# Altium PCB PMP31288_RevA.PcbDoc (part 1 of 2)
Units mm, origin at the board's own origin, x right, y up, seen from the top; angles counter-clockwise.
Board outline 73.66 x 62.23 mm, 2 copper layers (Top Layer, Bottom Layer), stack 1.575 mm thick; 96 components, 44 nets, 195 pads, 25 vias.
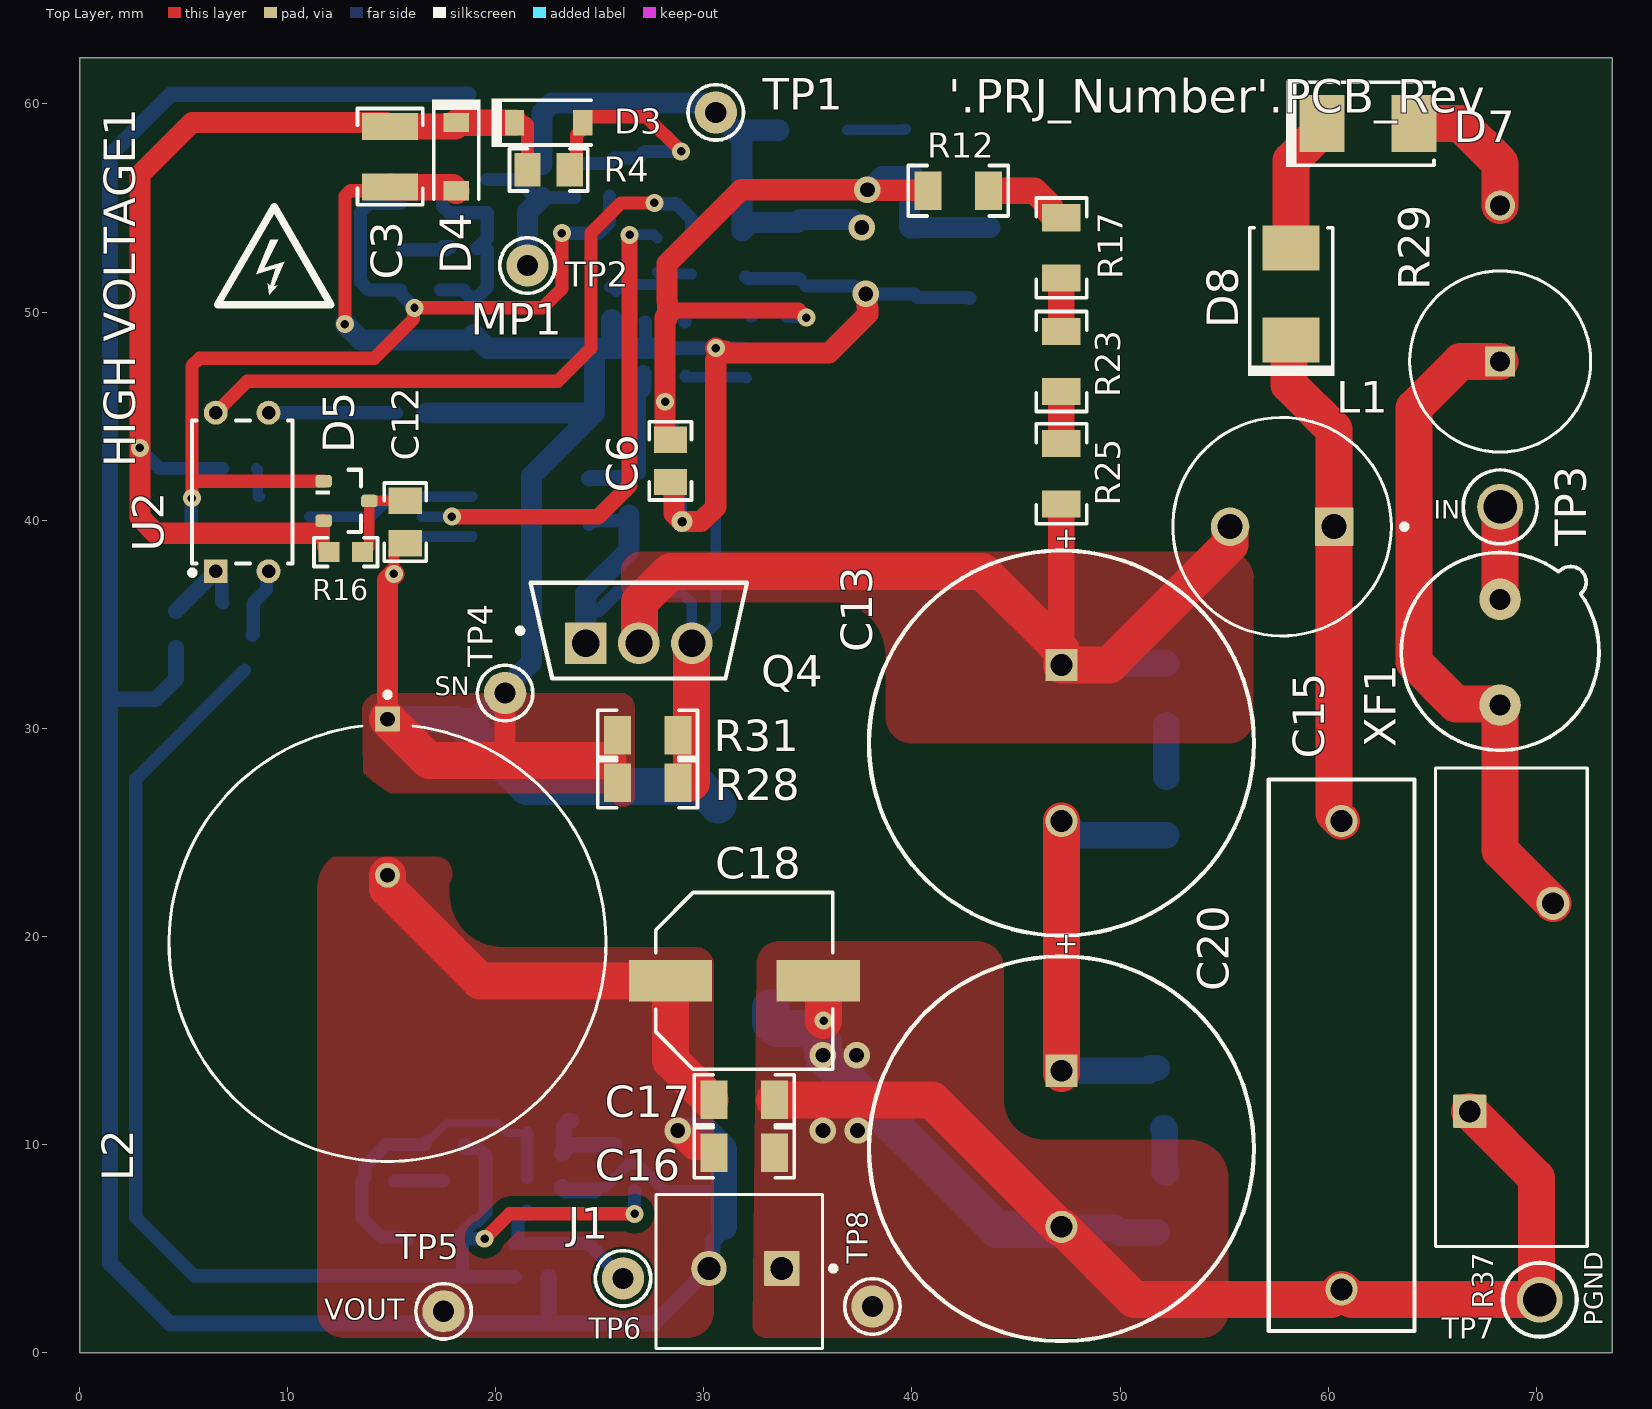
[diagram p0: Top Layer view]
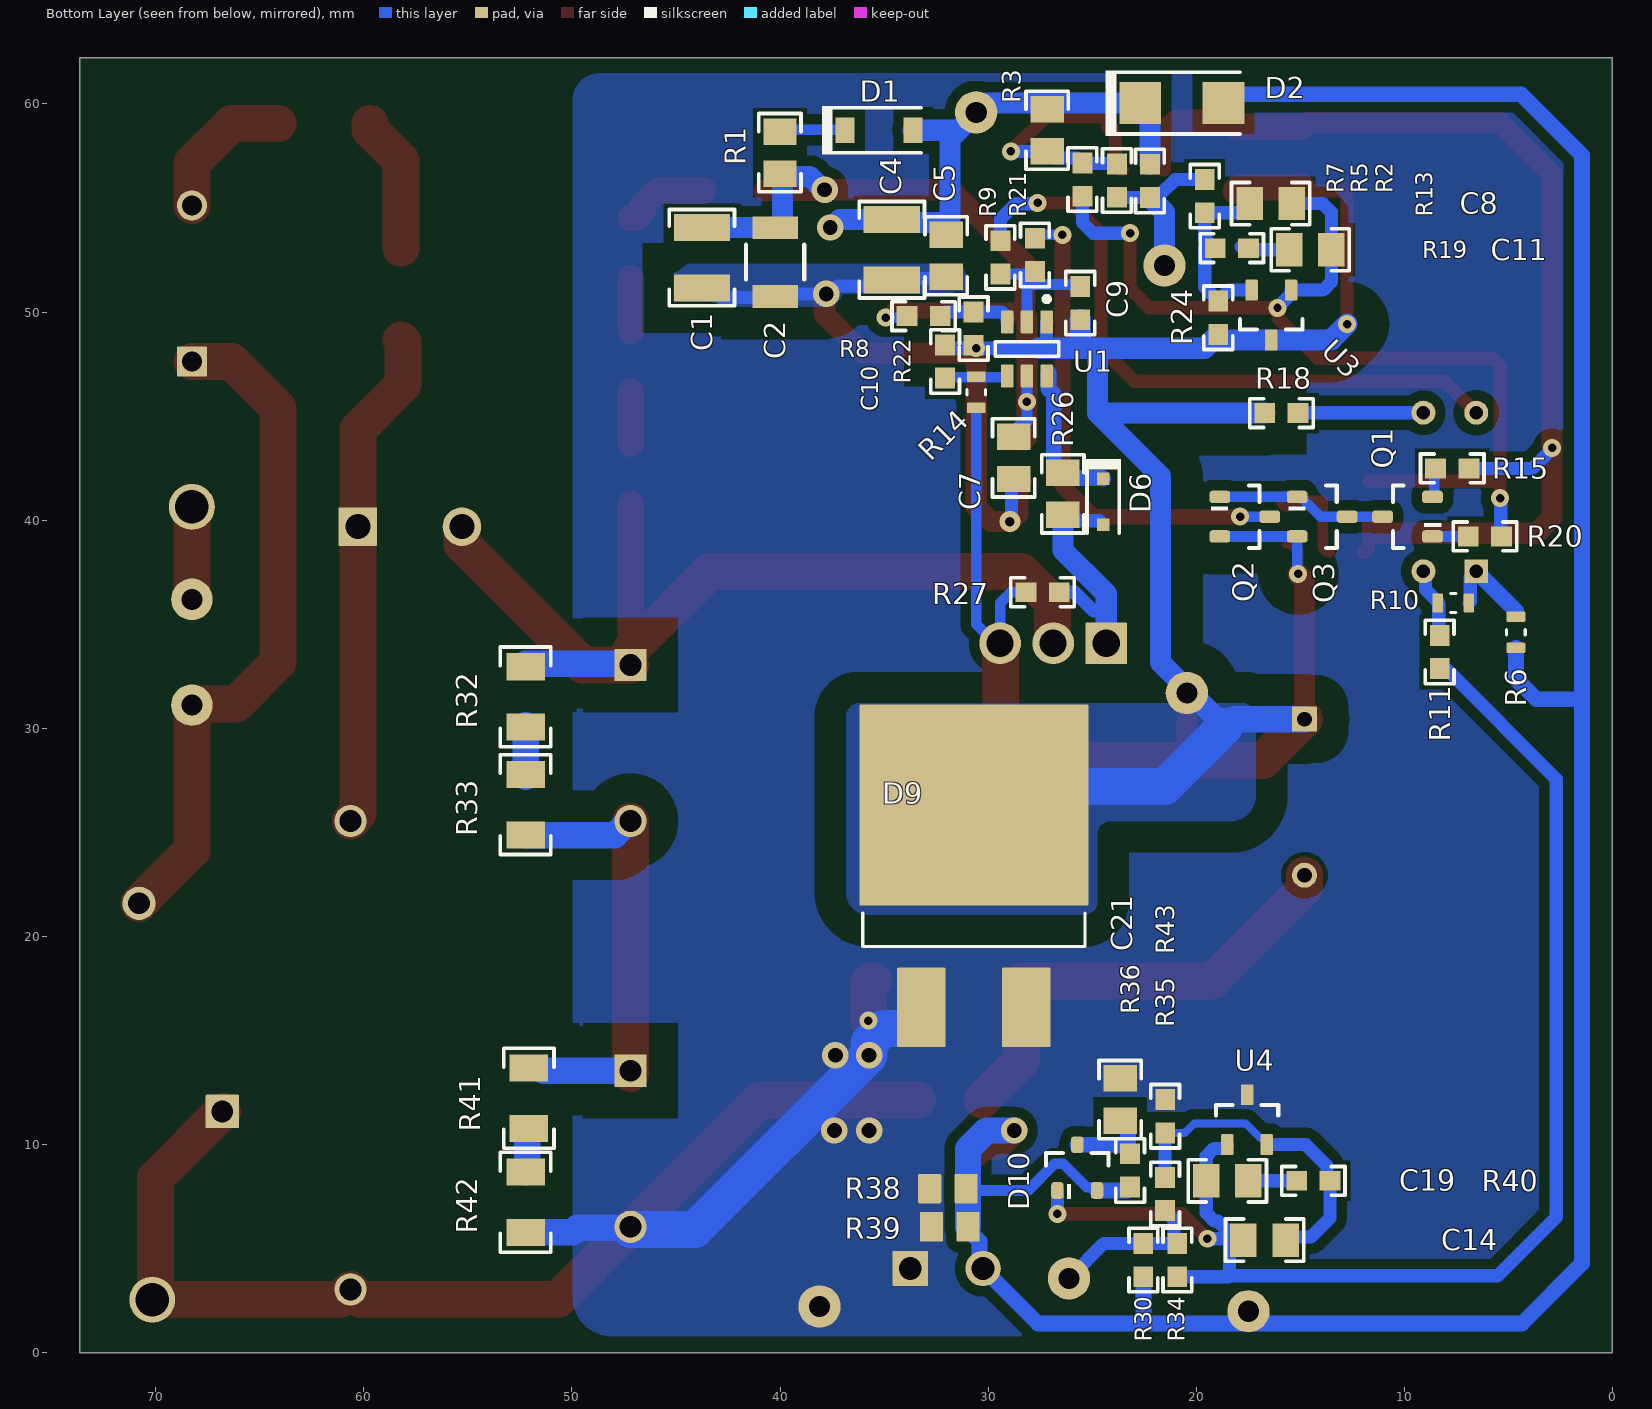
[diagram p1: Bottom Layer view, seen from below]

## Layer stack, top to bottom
Top Solder: solder mask 0.0102, Solder Resist, Dk 3.5
Top Layer: signal copper 0.0356
Dielectric1: core 1.5037, FR-4 High Tg, Dk 4.8
Bottom Layer: signal copper 0.0356
Bottom Solder: solder mask 0.0102, Solder Resist, Dk 3.5

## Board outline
0,0 73.66,0 73.66,62.23 0,62.23

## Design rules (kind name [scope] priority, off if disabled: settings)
AcuteAngle [All] p1: minimum=4.50000000000000E+0001 checktracksonly=FALSE
AssemblyTestPointUsage [All] p1: valid=2
BoardOutlineClearance BoardOutlineClearance_MountingHoles [OnCopper and InComponentClass('Mounting Holes')] p1: gap=1 ignorepadtopadclearanceinfootprint=FALSE
BoardOutlineClearance BoardOutlineClearance_Poly [OnCopper and IsPoly] p2: gap=0.635 ignorepadtopadclearanceinfootprint=FALSE
BoardOutlineClearance [OnCopper and Not InComponentClass('Logo') and not InComponentClass('FiducialMark') and not InRegion(1000,500,4000,800) and not InPoly] p3: gap=0.889 ignorepadtopadclearanceinfootprint=FALSE
Clearance Clearance_SN [InNet('SN') vs InNet('PGND')] p1: gap=1.524 ignorepadtopadclearanceinfootprint=TRUE
Clearance Clearance_C13_1 [InNet('NetC13_1') vs InNet('PGND')] p2: gap=1.524 ignorepadtopadclearanceinfootprint=TRUE
Clearance Clearance_C13_2 [InNet('NetC13_2') vs InNet('PGND')] p3: gap=1.524 ignorepadtopadclearanceinfootprint=TRUE
Clearance Clearance_Keepouts [((IsTrack Or IsArc) And Not InPoly) And IsFree and IsKeepOut vs ((IsTrack Or IsArc) And Not InPoly) And IsFree and IsKeepOut] p4: gap=0 ignorepadtopadclearanceinfootprint=FALSE
Clearance Clearance_Poly [InPolygon] p5: gap=0.508 ignorepadtopadclearanceinfootprint=TRUE
Clearance Clearance_FiducialMark [IsKeepOut and InComponentClass('FiducialMark') vs IsPad and InComponentClass('FiducialMark')] p6: gap=0 ignorepadtopadclearanceinfootprint=FALSE
Clearance [All] p7: gap=0.2 ignorepadtopadclearanceinfootprint=TRUE
ComponentClearance ComponentClearance_MountingHoles_FiducialMarks [InComponentClass('Mounting Holes') vs InComponentClass('FiducialMark')] p1: gap=1.27 collisioncheckmode=3 verticalgap=0.254 showdistances=FALSE
ComponentClearance ComponentClearance_Shunt [InComponentClass('Header') vs InComponentClass('Shunt')] p2: gap=0 collisioncheckmode=3 verticalgap=0 showdistances=FALSE
ComponentClearance ComponentClearance_Logo [InComponentClass('Logo')] p3: gap=0.762 collisioncheckmode=3 verticalgap=0.254 showdistances=FALSE
ComponentClearance ComponentClearance_ScrewToNut [(HasFootprint('NY PMS 440 0025 PH')) vs (HasFootprint('Keystone_1902C'))] p4: gap=0.127 collisioncheckmode=3 verticalgap=0.254 showdistances=FALSE
ComponentClearance ComponentClearance_MountingHoles [InComponentClass('Mounting Holes')] p5: gap=2.54 collisioncheckmode=3 verticalgap=2540 showdistances=FALSE
ComponentClearance ComponentClearance_SmallPassives [HasFootprint('0201*') or HasFootprint('0402*') or HasFootprint('0508') or HasFootprint('0603*') or HasFootprint('0612') or HasFootprint('0805*') or HasFootprint('0815*') or HasFootprint('0830*') or HasFootprint('1206*') or HasFootprint('1210*') or HasFootprint('1808*') or HasFootprint('1812*') or HasFootprint('1825*') or HasFootprint('2010*') or HasFootprint('2220*') or HasFootprint('2225*') or HasFootprint('2512*') or HasFootprint('2728*') or HasFootprint('3518*') vs HasFootprint('0201*') or HasFootprint('0402*') or HasFootprint('0508') or HasFootprint('0603*') or HasFootprint('0612') or HasFootprint('0805*') or HasFootprint('0815*') or HasFootprint('0830*') or HasFootprint('1206*') or HasFootprint('1210*') or HasFootprint('1808*') or HasFootprint('1812*') or HasFootprint('1825*') or HasFootprint('2010*') or HasFootprint('2220*') or HasFootprint('2225*') or HasFootprint('2512*') or HasFootprint('2728*') or HasFootprint('3518*')] p6: gap=0.38 collisioncheckmode=3 verticalgap=0.254 showdistances=FALSE
ComponentClearance ComponentClearance_THtoSMT [IsThruComponent vs IsSMTComponent] p7: gap=0.762 collisioncheckmode=3 verticalgap=0.762 showdistances=FALSE
ComponentClearance ComponentClearance_THtoTH [IsThruComponent vs IsThruComponent] p8: gap=0.508 collisioncheckmode=3 verticalgap=0.762 showdistances=FALSE
ComponentClearance [All] p9: gap=0.508 collisioncheckmode=3 verticalgap=0.254 showdistances=FALSE
DiffPairsRouting [All] p1: maxlimit=2.54 minlimit=0.254 mostfreqgap=0.254 toplayer_minwidth=0.381 toplayer_maxwidth=0.381 toplayer_prefwidth=0.381 bottomlayer_minwidth=0.381 bottomlayer_maxwidth=0.381 bottomlayer_prefwidth=0.381 maxuncoupledlength=25.4
FabricationTestPointUsage TestPointUsage [All] p1: valid=2 allowmultiple=FALSE
FabricationTestpoint Testpoint [All] p1: side=3 testpointundercomponent=TRUE minsize=1.016 maxsize=2.54 preferedsize=1.524 minholesize=0 maxholesize=1.016 preferedholesize=0.813 testpointgrid=0.025 allowsidetop=TRUE allowsidebottom=TRUE usegrid=TRUE gridtolerance=0
FanoutControl Fanout_LCC [IsLCC] p1: bgadir=Out bgaviamode=Centered fanoutstyle=Auto fanoutdirection=Alternating viagrid=0.025 // Fanout_LCC (Default Rule)
FanoutControl Fanout_BGA [IsBGA] p2: bgadir=Out bgaviamode=Centered fanoutstyle=Auto fanoutdirection=Alternating viagrid=0.025 // Fanout_BGA (Default Rule)
FanoutControl Fanout_Default [All] p4: bgadir=Out bgaviamode=Centered fanoutstyle=Auto fanoutdirection=Alternating viagrid=0.025 // Fanout_Default (Default Rule)
FanoutControl Fanout_Small [(CompPinCount < 5)] p5: bgadir=Out bgaviamode=Centered fanoutstyle=Auto fanoutdirection=OutThenIn viagrid=0.025 // Fanout_Small (Default Rule)
HoleSize [All] p1: absolutevalues=TRUE maxlimit=6.375 minlimit=0.2 maxpercent=80.000 minpercent=20.000
MinimumAnnularRing MinimumAnnularRing_ThermalPadVias [IsVia and InAnyComponent] p1: minimumring=0.15
MinimumAnnularRing [All] p2: minimumring=0.2
MinimumSolderMaskSliver MinimumSolderMaskSliver_Logo [InComponentClass('Logo') vs InComponentClass('Logo')] p1: minsoldermaskwidth=0.018
MinimumSolderMaskSliver [All] p2: minsoldermaskwidth=0.1
PlaneConnect [All] p1: planeconnectstyle=Relief reliefexpansion=0.254 reliefentries=4 reliefconductorwidth=0.254 reliefairgap=0.254
PolygonConnect [All] p1: connectstyle=Direct reliefconductorwidth=0.254 reliefentries=4 polygonreliefangle="90 Angle" airgapwidth=0.254
RoutingVias ThermalPadVias [IsVia and InAnyComponent] p1: holewidth=0.2 width=0.5 viastyle="Through Hole" minholewidth=0.2 minwidth=0.5 maxholewidth=0.33 maxwidth=0.6
RoutingVias [All] p2: holewidth=0.406 width=0.864 viastyle="Through Hole" minholewidth=0.2 minwidth=0.61 maxholewidth=1.016 maxwidth=1.651
SilkToBoardRegionClearance [Not ((IsComment or IsDesignator) And (Hide <> 'False')) and not InRegion(1000,500,4000,800)] p1:
SilkToSilkClearance SilkToSilkClearance_Pb-FreeLogo [(HasFootprint('Pb-Free_Overlay_Medium') OR HasFootprint('Pb-Free_Overlay_Small')) vs (HasFootprint('Pb-Free_Overlay_Medium') OR HasFootprint('Pb-Free_Overlay_Small'))] p1 off: silktosilkclearance=0
SilkToSilkClearance [All] p2 off: silktosilkclearance=0.1
SilkToSolderMaskClearance SilkToComponentPadClearance [(IsPad or IsFill or IsRegion) and InAnycomponent] p1 off: minsilkscreentomaskgap=0.127 clearancetoexposedcopper=TRUE
SilkToSolderMaskClearance "Silk to Solder Mask Opening" [All] p2 off: minsilkscreentomaskgap=0.1 clearancetoexposedcopper=FALSE
SolderMaskExpansion [All] p1: expansion=0.05 istentingtop=FALSE
UnRoutedNet [All] p1: checkbadconnections=TRUE
Width [All] p1: maxlimit=2.54 minlimit=0.152 preferedwidth=0.254 checkconnectedcopper=TRUE
14 further rules are at their usual default settings.

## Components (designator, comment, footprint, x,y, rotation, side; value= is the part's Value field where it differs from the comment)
C1 "DNPC3225X7R1H105K160AA" 1210_180 43.756,52.614 r270 bottom value=DNP
C2 "C3225X7R1H106M250AC" 1210_280 40.234,52.403 r270 bottom value=10uF
C3 "C3225X7R1H105K160AA" 1210_180 14.922,57.468 r270 top value=1uF
C4 "DNPC3225X7R1H105K160AA" 1210_180 34.63,52.995 r270 bottom value=DNP
C5 "GRM21BR71H224KA01L" 0805_HV 32.017,52.706 r270 bottom value=0.22uF
C6 "C0805C104J5RACTU" 0805_HV 28.394,42.851 r270 top value=1uF
C7 "C0805C104J5RACTU" 0805_HV 28.773,42.994 r270 bottom value=0.1uF
C8 "DNP08055C473KAT2A" 0805_HV 16.422,55.214 r180 bottom value=DNP
C9 "DNP" 0603 25.575,50.428 r270 bottom
C10 "C0603C391K5RACTU" 0603 32.067,47.625 r90 bottom value=390pF
C11 "08055C473KAT2A" 0805_HV 14.522,52.995 r180 bottom value=0.047uF
C12 "GRM21BR71H224KA01L" 0805_HV 15.65,39.911 r270 top value=0.22uF
C13 "UCS2W330MHD6" UCS_1800x2000 47.184,29.29 r270 top value=33uF
C14 "DNP08055C473KAT2A" 0805_HV 16.716,5.402 r0 bottom value=DNP
C15 "B32913C5104K000" B32913_2650x700x1600 60.642,14.287 r270 top value=0.1uF
C16 "GCM31MR71E105KA37L" 1206 31.944,9.605 r0 top value=DNP
C17 "GCM31MR71E105KA37L" 1206 31.944,12.145 r0 top value=DNP
C18 "EEE-FK1E331P" SM_RADIAL_F 31.944,17.86 r0 top value=330uF
C19 "08055C473KAT2A" 0805_HV 18.506,8.255 r0 bottom value=0.047uF
C20 "UCS2W330MHD6" UCS_1800x2000 47.184,9.795 r270 top value=33uF
C21 "GRM21BR71H105KA12L" 0805_HV 23.652,12.157 r90 bottom value=1uF
D1 "1N4148W-7-F" SOD-123 35.242,58.737 r180 bottom value=100V
D2 "US1M-13-F" SMA 20.691,60.045 r180 bottom value=1000V
D3 "DNP" SOD-123 22.543,59.105 r0 top value=100V
D4 "DNP" SOD-123 18.098,57.468 r270 top
D5 "BAV99-7-F" SOT-23L 12.828,40.925 r0 top value=75V
D6 "MMDL914-TP" SOD-323 24.476,40.892 r270 bottom value=100V
D7 "S1MB-13-F" SMB 61.912,59.055 r0 top value=1000V
D8 "S1MB-13-F" SMB 58.219,50.872 r90 top value=1000V
D9 "VS-10ETS08STRL-M3" FP-VS-10ETS08STRL-M3_D2PAK-MFG 30.689,24.342 r180 bottom
D10 "BAV99-7-F" SOT-23L 25.717,8.89 r90 bottom value=75V
"HIGH VOLTAGE1" "DANGER HIGH VOLTAGE" IEC_HighVoltage_Small 9.346,52.595 r0 top
J1 "691214110002S" FP-691214110002S_HDR2-MFG 31.694,3.89 r180 top
L1 "7687480121" FP-7687480121_RADIAL-MFG 57.785,39.688 r180 top value=SHORT
L2 "PT35002L" FP-PT35002L_PTH_D21MM0-MFG 14.799,19.69 r90 top
MP1 "HSS-B20-NP-06" FP-HSS-B20-NP-06_HEATSINK_19MM0_9MM52-MFG 26.829,43.021 r90 top
Q1 "MMBT2907ALT1G" SOT-23 9.846,40.167 r0 bottom value="60 V"
Q2 "SMBT 2222A E6327" SOT-23 17.666,40.167 r180 bottom value="40 V"
Q3 "SMBT 2222A E6327" SOT-23 13.95,40.167 r180 bottom value="40 V"
Q4 "STP80N240K6" FP-STP7N105K5_TO-220AB-MFG 26.874,34.69 r90 top
R1 "CRCW08050000Z0EAHP" 0805_HV 40.005,57.658 r270 bottom value=0
R2 "RC0603FR-0749R9L" 0603 22.225,56.299 r90 bottom value=DNP
R3 "CRCW08050000Z0EAHP" 0805_HV 27.166,58.737 r270 bottom value=DNP
R4 "CRCW08050000Z0EAHP" 0805_HV 22.543,56.832 r180 top value=0
R5 "DNP" 0603 23.812,56.321 r90 bottom
R6 "CRCW06031K00FKEAC" FP-CRCW06031K00FKEAC_0603-MFG 4.639,34.615 r270 bottom value=1k
R7 "DNP" 0603 25.465,56.369 r90 bottom
R8 "DNP" 0603 33.099,49.806 r0 bottom
R9 "CRCW06030000Z0EA" 0603 29.408,52.629 r270 bottom value=0
R10 "CRCW06031K00FKEAC" FP-CRCW06031K00FKEAC_0603-MFG 7.646,36.019 r180 bottom value=1k
R11 "CRCW06030000Z0EA" 0603 8.303,33.665 r90 bottom value=0
R12 "CRCW1206499KFKEA" 1206 42.227,55.83 r180 top value=499k
R13 "RC0603FR-07140KL" 0603 19.589,55.569 r90 bottom value=140k
R14 "CRCW06031K00FKEAC" FP-CRCW06031K00FKEAC_0603-MFG 30.574,46.148 r270 bottom value=1k
R15 "DNP" 0603 7.696,42.485 r180 bottom
R16 "RCG060310K0FKEA" 0603 12.793,38.47 r180 top value=10.0k
R17 "CRCW1206499KFKEA" 1206 47.184,53.082 r90 top value=499k
R18 "CRCW06030000Z0EA" 0603 15.907,45.145 r180 bottom value=0
R19 "CRCW06030000Z0EA" 0603 18.289,53.069 r180 bottom value=0
R20 "CRCW06030000Z0EA" 0603 6.128,39.217 r0 bottom value=0
R21 "DNP" 0603 27.753,52.746 r270 bottom
R22 "DNP" 0603 30.697,49.203 r90 bottom
R23 "CRCW1206499KFKEA" 1206 47.184,47.625 r90 top value=499k
R24 "RC0603FR-0735K7L" 0603 18.941,49.729 r90 bottom value=35.7k
R25 "CRCW1206499KFKEA" 1206 47.184,42.227 r90 top value=499k
R26 "CRCW080510R0JNEA" 0805_HV 26.408,41.267 r90 bottom value=10
R27 "CRCW0603100KFKEA" 0603 27.384,36.535 r0 bottom value=100k
R28 "ERJ-8RQFR82V" 1206 27.299,27.385 r180 top value=0.82
R29 "Z35092238209J6BC10_VM" FP-Z35092238209J6BC10_VM_AXIAL-MFG 68.263,47.625 r90 top value=TBD
R30 "RC0603FR-0749R9L" 0603 22.543,4.445 r270 bottom value=49.9
R31 "DNP" 1206 27.299,29.662 r0 top
R32 "CRCW12061M00JNEA" 1206 52.229,31.505 r90 bottom value=1.0Meg
R33 "CRCW12061M00JNEA" 1206 52.229,26.332 r90 bottom value=1.0Meg
R34 "DNP" 0603 20.908,4.445 r90 bottom
R35 "RC0603FR-07140KL" 0603 21.501,7.62 r270 bottom value=140k
R36 "RCG060310K0FKEA" 0603 23.177,8.752 r270 bottom value=10.0k
R37 "V20H510AUTO" FP-V20H510AUTO_RADIAL-MFG 68.802,16.59 r90 top
R38 "CRCW08054K99FKEAHP" FP-CRCW08054K99FKEAHP_0805-IPC_B 31.93,7.88 r180 bottom
R39 "CRCW08054K99FKEAHP" FP-CRCW08054K99FKEAHP_0805-IPC_B 31.844,6.045 r180 bottom
R40 "CRCW06030000Z0EA" 0603 14.371,8.255 r0 bottom value=0
R41 "CRCW12061M00JNEA" 1206 52.07,12.224 r90 bottom value=1.0Meg
R42 "CRCW12061M00JNEA" 1206 52.229,7.225 r90 bottom value=1.0Meg
R43 "RC0603FR-0735K7L" 0603 21.493,11.357 r270 bottom value=35.7k
TP1 "5000" Keystone5000 30.574,59.596 r0 top
TP2 "5000" Keystone5000 21.526,52.236 r90 top
TP3 "5125" Keystone5125 68.263,40.64 r0 top
TP4 "5000" Keystone5000 20.45,31.693 r90 top
TP5 "5000" Keystone5000 17.493,1.985 r90 top
TP6 "5000" Keystone5000 26.116,3.568 r90 top
TP7 "5127" Keystone5127 70.168,2.54 r0 top
TP8 "5001" Keystone5001 38.1,2.217 r90 top
U1 "UCC28750XDBV" DBV0006A-MFG 28.134,48.226 r270 bottom
U2 "FOD817A" DIP-4 7.814,41.355 r90 top
U3 "TL431AQDBZR" DBZ0003A_N 16.392,49.856 r270 bottom
U4 "TL431AQDBZR" DBZ0003A_N 17.556,11.192 r90 bottom
XF1 "56000001009" FuseHolder_560000010 68.263,33.655 r90 top value=TR5

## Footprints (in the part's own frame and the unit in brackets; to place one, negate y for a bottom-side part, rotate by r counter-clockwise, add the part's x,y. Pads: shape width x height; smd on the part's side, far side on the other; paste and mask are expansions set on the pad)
0603 [mm] "0603 from SM-752 data"
  rect 1x0.95 smd: 1(-0.8,0) 2(0.8,0)
  silkscreen extent -1.52,-0.69 1.52,0.69, body extent -0.87,-0.47 0.87,0.47, height 1
0805_HV [mil] "0805 with 30mil clearance between pads"
  rect 50x63 smd: 1(-40,0) 2(40,0)
  silkscreen extent -74,-40 74,40, body extent -43,-29 43,29, height 57
1206 [mm] "1206 from SM-752 data"
  rect 1.3x1.85 smd: 1(-1.45,0) 2(1.45,0)
  silkscreen extent -2.4,-1.21 2.4,1.21, body extent -1.7,-0.9 1.7,0.9, height 1.35
1210_180 [mm] "1210"
  rect 1.3x2.7 smd: 1(-1.45,0) 2(1.45,0)
  silkscreen extent -2.32,-1.57 2.32,1.57, body extent -1.7,-1.35 1.7,1.35, height 1.8
1210_280 [mm] "SMD, 2-Leads, Body 3.6x2.8mm, Height 2.8mm"
  rect 1.1x2.2 smd: 1(-1.65,0) 2(1.65,0)
  silkscreen extent -0.84,-1.4 0.84,1.4, body extent -1.8,-1.4 1.8,1.4, height 2.8
B32913_2650x700x1600 [mm] "TH, 2-Leads, Body 26.5x7mm, Pin Spacing 22.5mm"
  round 1.55 hole 1.05: 1(-11.25,0) 2(11.25,0)
  silkscreen extent -13.25,-3.5 13.25,3.5, body extent -13.25,-3.5 13.25,3.5, height 16
DBV0006A-MFG [mm]
  rrect17% 1.1x0.6 smd paste+0 mask+0: 1(-1.3,0.95) 2(-1.3,0) 3(-1.3,-0.95) 4(1.3,-0.95) 5(1.3,0) 6(1.3,0.95)
  silkscreen extent -2.52,-1.53 0.35,1.53, body extent -1.4,-1.45 1.4,1.45, height 1.45
DBZ0003A_N [mm] "SOT23, 3-Leads, Body 2.9x1.3mm, Pitch 0.95mm, Lead Span 2.4mm, IPC Medium Density"
  rrect17% 1x0.6 smd: 1(-1.2,0.95) 2(-1.2,-0.95) 3(1.2,0)
  silkscreen extent 0.2,-1.5 0.7,1.5, body extent -1.26,-1.46 1.26,1.46, height 0.98
DIP-4 [mm] "DIP, 4-Leads, Body 6.86x4.83mm, Pitch 2.54mm"
  rect 1.15x1.15 hole 0.65: 1(-3.81,1.27)
  round 1.15 hole 0.65: 2(-3.81,-1.27) 3(3.81,-1.27) 4(3.81,1.27)
  silkscreen extent -4,-2.41 3.43,2.52, body extent -4.02,-2.41 4.02,2.41, height 5.59
FP-7687480121_RADIAL-MFG [mm]
  rrect5% 1.85x1.85 hole 1.2 paste-2539.97 mask+0: 1(-2.5,0)
  round 1.85 hole 1.2 paste-2539.97 mask+0: 2(2.5,0)
  silkscreen extent -6,-5.25 5.25,5.25, body extent -5.35,-5.35 5.35,5.35, height 0.25
FP-691214110002S_HDR2-MFG [mm]
  rrect6% 1.7x1.7 hole 1.1 paste-2539.97 mask+0: 1(-2.05,-0.15)
  round 1.7 hole 1.1 paste-2539.97 mask+0: 2(1.45,-0.15)
  silkscreen extent -4.65,-3.7 4,3.7, body extent -4.1,-3.8 4.1,3.8, height 0.25
FP-CRCW06031K00FKEAC_0603-MFG [mm]
  rrect20% 0.5x0.9 smd paste+0 mask+0: 1(-0.75,0) 2(0.75,0)
  silkscreen extent -0.13,-0.45 0.13,0.45, body extent -0.8,-0.4 0.8,0.4, height 0.55
FP-CRCW08054K99FKEAHP_0805-IPC_B [mm]
  rrect9% 1.106x1.408 smd paste+0 mask+0: 1(-0.876,0) 2(0.876,0)
  body extent -1,-0.62 1,0.63, height 0.6
FP-HSS-B20-NP-06_HEATSINK_19MM0_9MM52-MFG [mm]
  body extent -5.11,-9.85 5.11,9.85, height 0.25
FP-PT35002L_PTH_D21MM0-MFG [mm]
  rrect8% 1.2x1.2 hole 0.7 paste-2539.97 mask+0: 1(10.75,0)
  round 1.2 hole 0.7 paste-2539.97 mask+0: 2(3.25,0)
  silkscreen extent -10.5,-10.5 12.05,10.5, body extent -11.47,-11.47 11.47,11.47, height 0.25
FP-STP7N105K5_TO-220AB-MFG [mm]
  rrect5% 2x2 hole 1.3 paste-2539.97 mask+0: 1(-0.605,2.55)
  round 2 hole 1.3 paste-2539.97 mask+0: 2(-0.605,0) 3(-0.605,-2.55)
  silkscreen extent -2.3,-5.2 2.3,5.82, body extent -2.4,-5.3 2.4,5.3, height 0.25
FP-V20H510AUTO_RADIAL-MFG [mm]
  rrect6% 1.6x1.6 hole 1.05 paste-2539.97 mask+0: 1(-5,2)
  round 1.6 hole 1.05 paste-2539.97 mask+0: 2(5,-2)
  silkscreen extent -11.5,-3.65 11.5,3.65, body extent -11.6,-3.75 11.6,3.75, height 0.25
FP-VS-10ETS08STRL-M3_D2PAK-MFG [mm]
  rrect4% 2.32x3.81 smd paste+0 mask+0: 1(-2.525,-7.752) 3(2.525,-7.752)
  rrect1% 11x9.65 smd paste+0 mask+0: 4(0,1.967)
  silkscreen extent -5.34,-4.82 5.34,-3.23, body extent -5.08,-9.43 5.08,6.19, height 5.09
FP-Z35092238209J6BC10_VM_AXIAL-MFG [mm]
  rrect7% 1.45x1.45 hole 0.95 paste-2539.97 mask+0: 1(0,0)
  round 1.45 hole 0.95 paste-2539.97 mask+0: 2(7.5,0)
  silkscreen extent -4.35,-4.35 4.35,4.35, body extent -4.45,-4.45 8.32,4.45, height 0.25
FuseHolder_560000010 [mm] "Littelfuse fuse holder TR5"
  round 2 hole 1: 1(-2.54,0) 2(2.54,0)
  silkscreen extent -4.71,-4.75 4.79,4.75, body extent -4.75,-4.74 4.75,4.75, height 5.6
IEC_HighVoltage_Small [mm]
  silkscreen extent -2.72,-2.24 2.72,2.47
Keystone5000 [mil] "For Keystone 500x miniature loop terminals"
  round 80 hole 40: 1(0,0)
  silkscreen extent -52,-52 52,52, body extent -49,-49 49,49, height 182
Keystone5001 [mil] "For Keystone 500x miniature loop terminals"
  round 80 hole 40: 1(0,0)
  silkscreen extent -52,-52 52,52, body extent -49,-49 49,49, height 182
Keystone5125 [mil] "Keystone Multipurpose loops"
  round 87 hole 63: 1(0,0)
  silkscreen extent -70,-70 70,70, body extent -63,-63 63,62, height 319
Keystone5127 [mil] "Keystone Multipurpose loops"
  round 87 hole 63: 1(0,0)
  silkscreen extent -70,-70 70,70, body extent -63,-63 63,62, height 319
SM_RADIAL_F [mm] "8 x 10.2mm:  Panasonic F"
  rect 4x2 smd: 1(-3.55,0) 2(3.55,0)
  silkscreen extent -4.25,-4.25 4.25,4.25, body extent -4.25,-4.25 4.25,4.25, height 10.5
SMA [mm] "Molded Diode, 2-Leads, Body 4.3x2.6mm, IPC Medium Density, based on OnSemi component dimensions and land pattern"
  rect 2x2 smd: 1(-2,0) 2(2,0)
  silkscreen extent -3.66,-1.57 2.79,1.57, body extent -2.6,-1.3 2.6,1.3, height 2.42
SMB [mm] "Molded Diode, 2-Leads, Body 5.4x3.6mm, IPC Medium Density, based on OnSemi component dimensions"
  rect 2.159x2.743 smd: 1(-2.21,0) 2(2.21,0)
  silkscreen extent -3.94,-2.08 3.17,2.08, body extent -2.7,-1.8 2.7,1.8, height 2.32
SOD-123 [mm] "On Semi recommended land pattern"
  rect 0.915x1.22 smd: 1(-1.637,0) 2(1.637,0)
  silkscreen extent -2.74,-1.17 2.03,1.17, body extent -1.93,-0.9 1.93,0.9, height 1.35
SOD-323 [mm] "NXP recommended land pattern"
  rect 0.6x0.6 smd paste-0.05: 1(-1.1,0) 2(1.1,0)
  silkscreen extent -2.06,-0.86 1.53,0.86, body extent -1.3,-0.67 1.3,0.68, height 1.1
SOT-23 [mm] "SOT23, 3-Leads, Body 2.9x1.3mm, Pitch 0.95mm, Lead Span 2.5mm, IPC Medium Density"
  rrect50% 1x0.6 smd: 1(-1.2,0.95) 2(-1.2,-0.95) 3(1.2,0)
  silkscreen extent -1.63,-1.5 0.7,1.5, body extent -1.16,-1.45 1.21,1.45, height 1
SOT-23L [mm] "SOT23, 3-Leads, Body 2.9x1.3mm, Pitch 0.95mm, Lead Span 2.5mm, IPC High Density"
  rrect50% 0.8x0.6 smd: 1(-1.1,0.95) 2(-1.1,-0.95) 3(1.1,0)
  silkscreen extent -1.5,-1.5 0.7,1.5, body extent -1.16,-1.45 1.21,1.45, height 1
UCS_1800x2000 [mm] "TH, 2-Leads, Dia 18mm, Lead Spacing 7.5mm"
  rect 1.55x1.55 hole 1.05: 1(-3.75,0)
  round 1.55 hole 1.05: 2(3.75,0)
  silkscreen extent -9.25,-9.25 9.25,9.25, body extent -9.18,-9.23 9.22,9.24, height 21.51

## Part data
C1 C4: library part CMP-0009119-1, "CAP, CERM,", Cap_Case=1210_180, Manufacturer=TDK, PartNumber=DNP, Supplier Part Number 1=445-7722-1-ND, TempCo=X7R, Tolerance_%=10%, Value1="0.007168 ohm", Value2=50V
C2: library part CMP-0009120-1, "CAP, CERM, 10 uF, 50 V, +/- 20%, X7R, 1210", Cap_Case=1210, Manufacturer=TDK, Supplier Part Number 1=445-14933-1-ND, TempCo=X7R, Tolerance_%=20%, Value1=Unknown, Value2=50V, ValueDisplayed=10uF
C3: library part CMP-0009119-1, "CAP, CERM, 1 uF, 50 V, +/- 10%, X7R, 1210", Cap_Case=1210_180, Manufacturer=TDK, Supplier Part Number 1=445-7722-1-ND, TempCo=X7R, Tolerance_%=10%, Value1="0.007168 ohm", Value2=50V, ValueDisplayed=DNP
C5 C12: library part CMP-0008354-1, "CAP, CERM, 0.22 uF, 50 V, +/- 10%, X7R, 0805", Cap_Case=0805, Manufacturer=MuRata, Supplier Part Number 1=490-1670-1-ND, TempCo=X7R, Tolerance_%=10%, Value1=Unknown, Value2=50V, ValueDisplayed=0.22uF
C6: library part CMP-0007721-2, "DNP", Cap_Case=0805, Manufacturer=Kemet, Supplier Part Number 1=64K2889, TempCo=X7R, Tolerance_%=5%, Value1="0.064 ohm", Value2=50V, ValueDisplayed=1uF
C7: library part CMP-0007721-2, "CAP, CERM, 0.1 uF, 50 V, +/- 5%, X7R, 0805", Cap_Case=0805, Manufacturer=Kemet, Supplier Part Number 1=64K2889, TempCo=X7R, Tolerance_%=5%, Value1="0.064 ohm", Value2=50V, ValueDisplayed=0.1uF
C8 C14: library part CMP-0007659-2, "CAP, CERM,", Cap_Case=0805, Manufacturer=AVX, PartNumber=DNP, Supplier Part Number 1=478-1391-1-ND, TempCo=X7R, Tolerance_%=10%, Value2=50V, ValueDisplayed=0.047uF
C9: library part CMP-0007144-4, "CAP, CERM,", Cap_Case=0603, Manufacturer=MuRata, Supplier Part Number 1=490-4779-1-ND, TempCo=X7R, Tolerance_%=10%, Value1="0.02 ohm", Value2=50V
C10: library part CMP-0006933-5, "CAP, CERM, 390 pF, 50 V, +/- 10%, X7R, 0603", Cap_Case=0603, Manufacturer=Kemet, Supplier Part Number 1=399-1074-1-ND, TempCo=X7R, Tolerance_%=10%, Value1=Unknown, Value2=50V, ValueDisplayed=390pF
C11 C19: library part CMP-0007659-2, "CAP, CERM, 0.047 uF, 50 V, +/- 10%, X7R, 0805", Cap_Case=0805, Manufacturer=AVX, Supplier Part Number 1=478-1391-1-ND, TempCo=X7R, Tolerance_%=10%, Value1="0.035 ohm", Value2=50V, ValueDisplayed=0.047uF
C13 C20: library part CMP-0010243-2, "CAP, AL, 33 uF, 450 V, +/- 20%, TH", Cap_Case=18x20mm, Manufacturer=Nichicon, Supplier Part Number 1=493-5885-ND, Tolerance_%=20%, Value1=Unknown, Value2=450V, ValueDisplayed=33uF
C15: library part CMP-0012372-3, "CAP, Film, 0.1 uF, 1000 V, +/- 10%, TH", Cap_Case=26.5x7x16mm, Manufacturer=TDK, Supplier Part Number 1=B32913C5104K-ND, Tolerance_%=10%, Value1=Unknown, Value2=1000V, ValueDisplayed=0.1uF
C16 C17: library part CMP-0008817-1, "DNP", Cap_Case=1206, Manufacturer=MuRata, Supplier Part Number 1=490-6066-1-ND, TempCo=X7R, Tolerance_%=10%, Value1=Unknown, Value2=25V
C18: library part CMP-0010717-1, "CAP, AL, 330 uF, 25 V, +/- 20%, 0.16 ohm, AEC-Q200 Grade 2, SMD", Cap_Case=F, Manufacturer=Panasonic, Supplier Part Number 1=PCE3803CT-ND, Tolerance_%=20%, Value1="0.16 ohm", Value2=25V, ValueDisplayed=330uF
C21: library part CMP-0008350-2, "CAP, CERM, 1 uF, 50 V, +/- 10%, X7R, 0805", Cap_Case=0805, Manufacturer=MuRata, Supplier Part Number 1=490-4736-1-ND, TempCo=X7R, Tolerance_%=10%, Value1=Unknown, Value2=50V, ValueDisplayed=1uF
D1: library part CMP-0029001-1, "Diode, Ultrafast, 100 V, 0.15 A, SOD-123", Manufacturer="Diodes Inc.", Supplier Part Number 1=1N4148W-FDICT-ND, Value1=0.15A, Value2=1.25V
D2: library part CMP-0076882-2, "Diode, Ultrafast, 1000 V, 1 A, SMA", Manufacturer="Diodes Inc.", Value1=1A, Value2=1.7V
D3: library part CMP-0029001-1, "Diode, Ultrafast, 100 V, 0.15 A, SOD-123", Manufacturer="Diodes Inc.", PartNumber=1N4148W-7-F, Supplier Part Number 1=1N4148W-FDICT-ND, Value1=0.15A, Value2=1.25V
D4: library part CMP-0005744-4, "Diode, Zener", Manufacturer="ON Semiconductor", Power_W=500mW, Value1=0.5W
D5 D10: library part CMP-0076900-2, "Diode, Switching, 75 V, 0.3 A, SOT-23", Manufacturer="Diodes Inc.", Value1=0.3A, Value2=1.25V
D6: library part CMP-0029045-1, "Diode, Switching, 100 V, 0.2 A, SOD-323", Manufacturer="Micro Commercial Components", Supplier Part Number 1=MMDL914-TPMSCT-ND, Value1=0.2A, Value2=1V
D7 D8: library part CMP-0077102-2, "Diode, Standard Recovery Rectifier, 1000 V, 1 A, SMB", Manufacturer="Diodes Inc.", Value1=1A, Value2=1.1V
D9: library part CMP-0001428-1, "Rectifier Diode Switching 800V 10A 3-Pin(2+Tab) D2PAK T/R", Digikey Part Number=112-VS-10ETS08STRL-M3CT-ND, Forward Current=10A, Manufacturer=Vishay, Max Surge Forward Current=160A, Mouser Part Number=78-VS-10ETS08STRL-M3, Operating Temperature Range="-40°C to +150°C", Part Number=TBD, Peak Reverse Current=0.05mA
"HIGH VOLTAGE1": library part CMP-0074835-1, "IEC 61010-1 High Voltage Warning"
J1: library part CMP-0093089-2, "2 Position Wire to Board Terminal Block Horizontal with Board 0.138\" (3.50mm) Through Hole", Current_A=10A, Digikey Part Number=732-691214110002S-ND, Manufacturer=Wurth, Mouser Part Number=710-691214110002S, Operating Temperature Range="-30°C to +120°C", Voltage_V=300V
L1: library part CMP-0095920-1, "WE-TI HV Radial Leaded Wire Wound Inductor (High Voltage) 120µH 10% 2A 0.18Ω", Manufacturer=Wurth, Operating Temperature Range="-40°C to +125°C", Self Resonant Frequency=3.1MHz, Test Frequency=100kHz, Tolerance_%=10%
L2: library part CMP-0091658-1, "Common mode choke 812uH ±10% 0.6Ω", Manufacturer=Bourns, Operating Temperature Range=to, Test Frequency=10kHz, Tolerance_%=10%
MP1: library part CMP-0091664-1, "Heat Sink TO-220 Aluminum 2.9W @ 75°C Board Level", Digikey Part Number=102-4186-ND, Manufacturer="CUI Devices", Mating Package=TO-220, Mouser Part Number=490-HSS-B20-NP-06, Natural Thermal Resistance=31.94°C/W, Operating Temperature Range=to, Thermal Resistance Forced Air Flow=5.84°C/W
Q1: library part CMP-0000344-2, "Transistor, PNP, 60 V, 0.6 A, SOT-23", Manufacturer="ON Semiconductor", Supplier Part Number 1=MMBT2907ALT1GOSCT-ND, Value1="0.6 A"
Q2 Q3: library part CMP-0000472-2, "Transistor, NPN, 40 V, 0.6 A, AEC-Q101, SOT-23", Manufacturer="Infineon Technologies", Supplier Part Number 1=SMBT2222AINCT-ND, Value1="0.6 A", Value2=300
Q4: library part CMP-0088481-1, "N-Channel 800V Through Hole TO-220", Drain To Source Breakdown Voltage=1050V, Manufacturer=STMicroelectronics, Operating Temperature Range="-55°C to +150°C"
R1 R4: library part CMP-0020443-2, "RES, 0, 5%, 0.333 W, 0805", Manufacturer=Vishay-Dale, Power_W=333mW, Supplier Part Number 1=541-0.0TBCT-ND, TempCo="200 ppm/C", Tolerance_%=5%, Value2=0.333W, Value_Code=0000, ValueDisplayed=0
R2: library part CMP-0023143-5, "DNP", Manufacturer=Yageo, Power_W=100mW, Supplier Part Number 1=311-49.9HRCT-ND, TempCo="100 ppm/C", Tolerance_%=1%, Value2=0.1W, Value_Code=49R9
R3: library part CMP-0020443-2, "RES, 0, 5%, 0.333 W, 0805", Manufacturer=Vishay-Dale, Power_W=333mW, Supplier Part Number 1=541-0.0TBCT-ND, TempCo="200 ppm/C", Tolerance_%=5%, Value2=0.333W, Value_Code=0000, ValueDisplayed=DNP
R5 R7 R8 R15 R21 R22 R34: library part CMP-0022796-4, "RES,", Manufacturer=Yageo, PartNumber=RC0603FR-07140KL, Power_W=100mW, Supplier Part Number 1=311-140KHRCT-ND, TempCo="100 ppm/C", Tolerance_%=1%, Value2=0.1W, Value_Code=140k
R6 R10 R14: library part CMP-0090742-1, "1 kOhms ±1% 0.1W, 1/10W Chip Resistor 0603 (1608 Metric) Thick Film", Digikey Part Number=541-3949-1-ND, Manufacturer=Vishay, Mouser Part Number=71-CRCW06031K00FKEAC, Operating Temperature Range="-55°C to +155°C", Power_W=100mW, TempCo=100ppm/°C, Tolerance_%=1%
R9 R11 R18 R19 R20 R40: library part CMP-0025697-1, "RES, 0, 5%, 0.1 W, 0603", Manufacturer=Vishay-Dale, Power_W=100mW, Supplier Part Number 1=541-0.0GCT-ND, TempCo="200 ppm/C", Tolerance_%=5%, Value2=0.1W, Value_Code=0000, ValueDisplayed=0
R12 R17 R23 R25: library part CMP-0017016-3, "RES, 499 k, 1%, 0.25 W, AEC-Q200 Grade 0, 1206", Manufacturer=Vishay-Dale, Power_W=250mW, Supplier Part Number 1=541-499KFCT-ND, TempCo="100 ppm/C", Tolerance_%=1%, Value2=0.25W, Value_Code=499k
R13 R35: library part CMP-0022796-4, "RES, 140 k, 1%, 0.1 W, 0603", Manufacturer=Yageo, Power_W=100mW, Supplier Part Number 1=311-140KHRCT-ND, TempCo="100 ppm/C", Tolerance_%=1%, Value2=0.1W, Value_Code=140k
R16 R36: library part CMP-0023337-3, "RES, 10.0 k, 1%, 0.1 W, 0603", Manufacturer="Vishay Draloric", Power_W=100mW, Supplier Part Number 1=541-1784-1-ND, TempCo="100 ppm/C", Tolerance_%=1%, Value2=0.1W, Value_Code=10k0, ValueDisplayed=10.0k
R24 R43: library part CMP-0023050-5, "RES, 35.7 k, 1%, 0.1 W, 0603", Manufacturer=Yageo, Power_W=100mW, Supplier Part Number 1=311-35.7KHRCT-ND, TempCo="100 ppm/C", Tolerance_%=1%, Value2=0.1W, Value_Code=35k7, ValueDisplayed=35.7k
R26: library part CMP-0020448-1, "RES, 10, 5%, 0.125 W, 0805", Manufacturer=Vishay-Dale, Power_W=125mW, Supplier Part Number 1=541-10ACT-ND, TempCo="200 ppm/C", Tolerance_%=5%, Value2=0.125W, Value_Code=10R0, ValueDisplayed=10
R27: library part CMP-0021990-3, "RES, 100 k, 1%, 0.1 W, 0603", Manufacturer=Vishay-Dale, Power_W=100mW, Supplier Part Number 1=541-100KHCT-ND, TempCo="100 ppm/C", Tolerance_%=1%, Value2=0.1W, Value_Code=100k
R28: library part CMP-0017794-3, "RES, 0.82, 1%, 0.25 W, AEC-Q200 Grade 0, 1206", Manufacturer=Panasonic, Power_W=250mW, Supplier Part Number 1=P.82RCT-ND, TempCo="250 ppm/C", Tolerance_%=1%, Value2=0.25W, Value_Code=R820, ValueDisplayed=0.82
R29: library part CMP-0091179-1, "Industrial Axial Cemented Leaded Wirewound Resistors  5% 6W", Manufacturer=Vishay, Operating Temperature Range=to, Power_W=6W, Tolerance_%=5%
R30: library part CMP-0023143-5, "RES, 49.9, 1%, 0.1 W, 0603", Manufacturer=Yageo, Power_W=100mW, Supplier Part Number 1=311-49.9HRCT-ND, TempCo="100 ppm/C", Tolerance_%=1%, Value2=0.1W, Value_Code=49R9, ValueDisplayed=49.9
R31: library part CMP-0017792-3, "RES, 0.56, 1%, 0.25 W, AEC-Q200 Grade 0, 1206", Manufacturer=Panasonic, Power_W=250mW, Supplier Part Number 1=P.56RCT-ND, TempCo="250 ppm/C", Tolerance_%=1%, Value2=0.25W, Value_Code=R560, ValueDisplayed=0.56
R32 R33 R41 R42: library part CMP-0018610-3, "RES, 1.0 M, 5%, 0.25 W, AEC-Q200 Grade 0, 1206", Manufacturer=Vishay-Dale, Power_W=250mW, Supplier Part Number 1=541-1.0MECT-ND, TempCo="200 ppm/C", Tolerance_%=5%, Value2=0.25W, Value_Code=1M00, ValueDisplayed=1.0M
R37: library part CMP-0090617-1, "820V 10kA Varistor 1 Circuit Through Hole Disc 20mm", Clamping Voltage=1355V, Digikey Part Number=F10974-ND, Manufacturer=Littelfuse, Mouser Part Number=576-V20H510AUTO, Operating Temperature Range="-40°C to +125°C", Part Number=TBD, ValueDisplayed=350pF, Varistor Voltage=738V
R38 R39: library part CMP-0086412-2, "Res Thick Film 0805 4.99K Ohm 1% 1/3W 100ppm/C Molded SMD SMD Paper T/R", Manufacturer="Vishay Dale", Power_W=500mW, TempCo=100ppm/°C, Tolerance_%=1%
